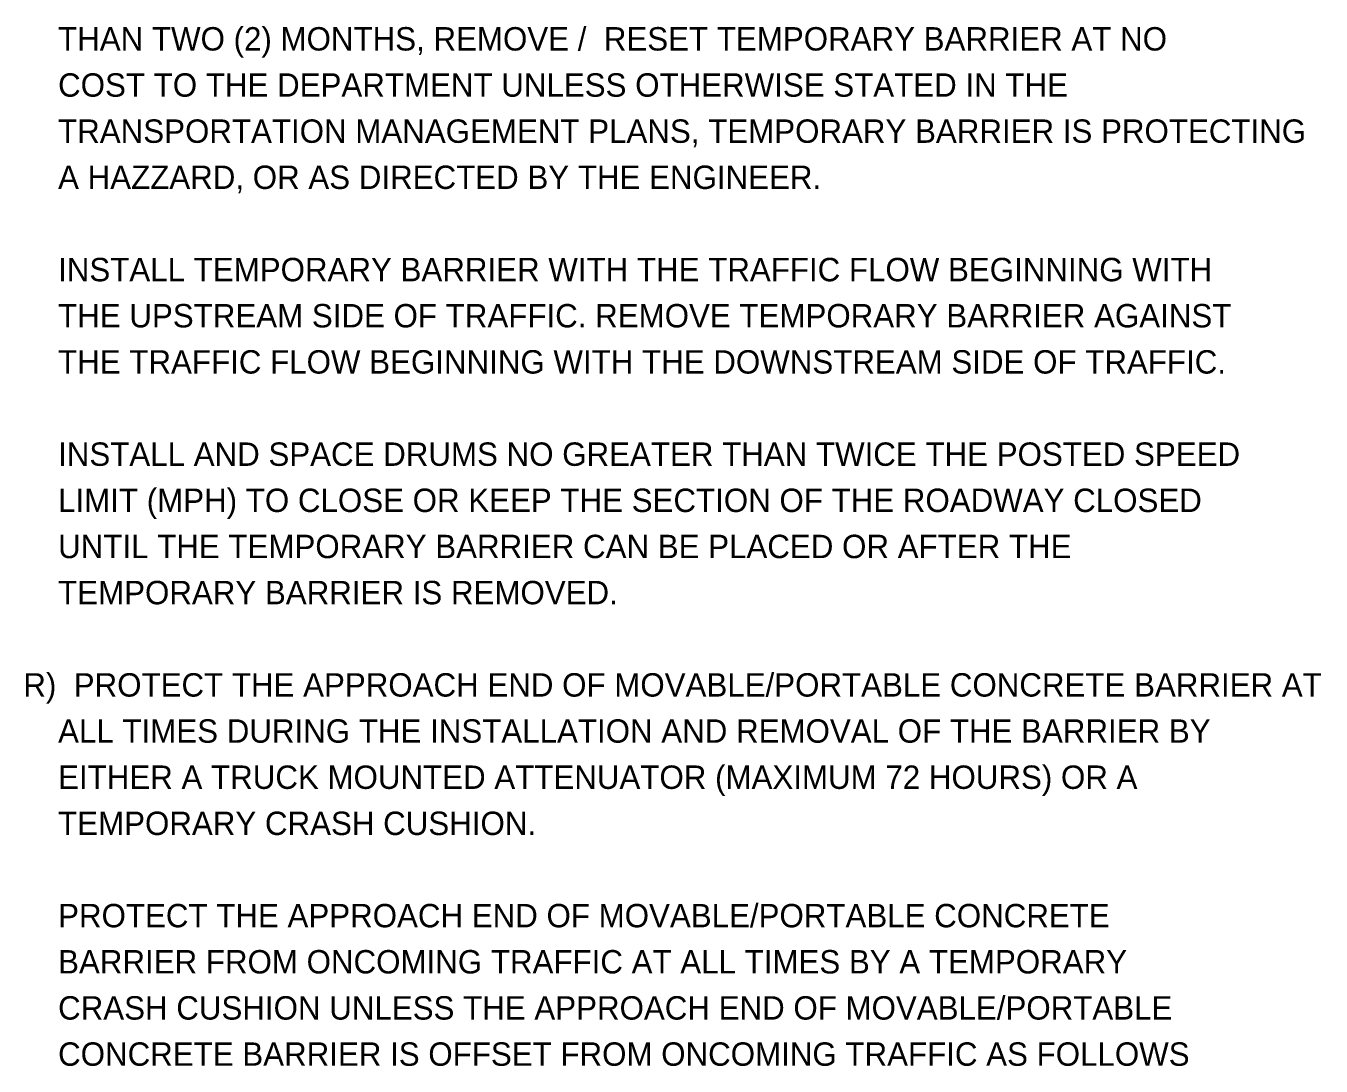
# Model space of a CAD drawing. Extents: x 762655 to 770567, y 650864 to 655190.
# Drawn here: x 763768.1 to 764100.2, y 653058.7 to 653325.4 of the extents above; entities that cross this region are included whole.
import ezdxf

# ---------------------------------------------------------------- set-up
doc = ezdxf.new("R2010")
doc.units = 0
doc.layers.add('Default', color=7, linetype='Continuous')

msp = doc.modelspace()

# ---------------------------------------------------------------- texts
at = {"layer": 'Default'}
for s, p in [('           THAN TWO (2) MONTHS, REMOVE /  RESET TEMPORARY BARRIER AT NO', (763751.79, 653319.11)), ('           COST TO THE DEPARTMENT UNLESS OTHERWISE STATED IN THE ', (763751.79, 653307.27)), ('           TRANSPORTATION MANAGEMENT PLANS, TEMPORARY BARRIER IS PROTECTING', (763751.79, 653295.44)), ('           A HAZZARD, OR AS DIRECTED BY THE ENGINEER.', (763751.79, 653283.61)), ('           INSTALL TEMPORARY BARRIER WITH THE TRAFFIC FLOW BEGINNING WITH', (763751.79, 653259.94)), ('           THE UPSTREAM SIDE OF TRAFFIC. REMOVE TEMPORARY BARRIER AGAINST', (763751.79, 653248.11)), ('           THE TRAFFIC FLOW BEGINNING WITH THE DOWNSTREAM SIDE OF TRAFFIC.', (763751.79, 653236.27)), ('           INSTALL AND SPACE DRUMS NO GREATER THAN TWICE THE POSTED SPEED', (763751.79, 653212.61)), ('           LIMIT (MPH) TO CLOSE OR KEEP THE SECTION OF THE ROADWAY CLOSED', (763751.79, 653200.77)), ('           UNTIL THE TEMPORARY BARRIER CAN BE PLACED OR AFTER THE ', (763751.79, 653188.94)), ('           TEMPORARY BARRIER IS REMOVED.', (763751.79, 653177.11)), ('       R)  PROTECT THE APPROACH END OF MOVABLE/PORTABLE CONCRETE BARRIER AT', (763751.79, 653153.44)), ('           ALL TIMES DURING THE INSTALLATION AND REMOVAL OF THE BARRIER BY', (763751.79, 653141.61)), ('           EITHER A TRUCK MOUNTED ATTENUATOR (MAXIMUM 72 HOURS) OR A ', (763751.79, 653129.77)), ('           TEMPORARY CRASH CUSHION.', (763751.79, 653117.94)), ('           PROTECT THE APPROACH END OF MOVABLE/PORTABLE CONCRETE', (763751.79, 653094.27)), ('           BARRIER FROM ONCOMING TRAFFIC AT ALL TIMES BY A TEMPORARY', (763751.79, 653082.44)), ('           CRASH CUSHION UNLESS THE APPROACH END OF MOVABLE/PORTABLE', (763751.79, 653070.61)), ('           CONCRETE BARRIER IS OFFSET FROM ONCOMING TRAFFIC AS FOLLOWS', (763751.79, 653058.77))]:
    msp.add_text(s, height=6, dxfattribs=at).set_placement(p)

doc.saveas('drawing.dxf')
